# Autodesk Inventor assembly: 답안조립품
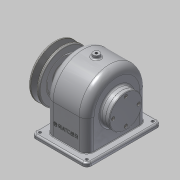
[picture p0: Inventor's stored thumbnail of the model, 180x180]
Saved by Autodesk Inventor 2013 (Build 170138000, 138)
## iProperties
Created: 2016-01
Part Number: 답안조립품
Document SubType Name: Assembly
Designer: Administrator
Author: Administrator
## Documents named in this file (16)
- C:\Users\Administrator\Desktop\460106V1024\답안조립품.iam
- C:\Users\Administrator\Desktop\460106V1024\본체.ipt
- C:\Users\Administrator\Desktop\460106V1024\베어링 6203.ipt
- C:\Users\Administrator\Desktop\460106V1024\뒤커버.ipt
- C:\Users\Administrator\Desktop\460106V1024\앞커버.ipt
- C:\Users\Administrator\Desktop\460106V1024\부시1.ipt
- C:\Users\Administrator\Desktop\460106V1024\축.ipt
- C:\Users\Administrator\Desktop\460106V1024\키 - 6 x 6 x 22.ipt
- C:\Users\Administrator\Desktop\460106V1024\스퍼기어.ipt
- C:\Users\Administrator\Desktop\460106V1024\키 - 5 x 5 x 18.ipt
- C:\Users\Administrator\Desktop\460106V1024\오일씰 28 40 8.ipt
- C:\Users\Administrator\Desktop\460106V1024\V-벨트풀리.ipt
- C:\Users\Administrator\Desktop\460106V1024\볼트 M3 x 8.ipt
- C:\Users\Administrator\Desktop\460106V1024\볼트 M3 x 10.ipt
- C:\Users\Administrator\Desktop\460106V1024\멈춤나사 - M4x10.ipt
- C:\Users\Administrator\Desktop\460106V1024\부시2.ipt
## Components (9 placed, 3 different names)
1. V-벨트풀리:1
2. ISO 4762 M3 x 8:1
3. ISO 4762 M3 x 8:2
4. ISO 4762 M3 x 8:3
5. ISO 4762 M3 x 8:4
6. ISO 4762 M3 x 10:1
7. ISO 4762 M3 x 10:2
8. ISO 4762 M3 x 10:3
9. ISO 4762 M3 x 10:4
